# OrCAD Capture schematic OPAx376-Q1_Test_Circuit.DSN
size A; title: OPAx376-Q1 Low-Noise, Low Quiescent Current, Precision; rev: 1.4; note: Datasheet: SBOS549C EVM: N/A
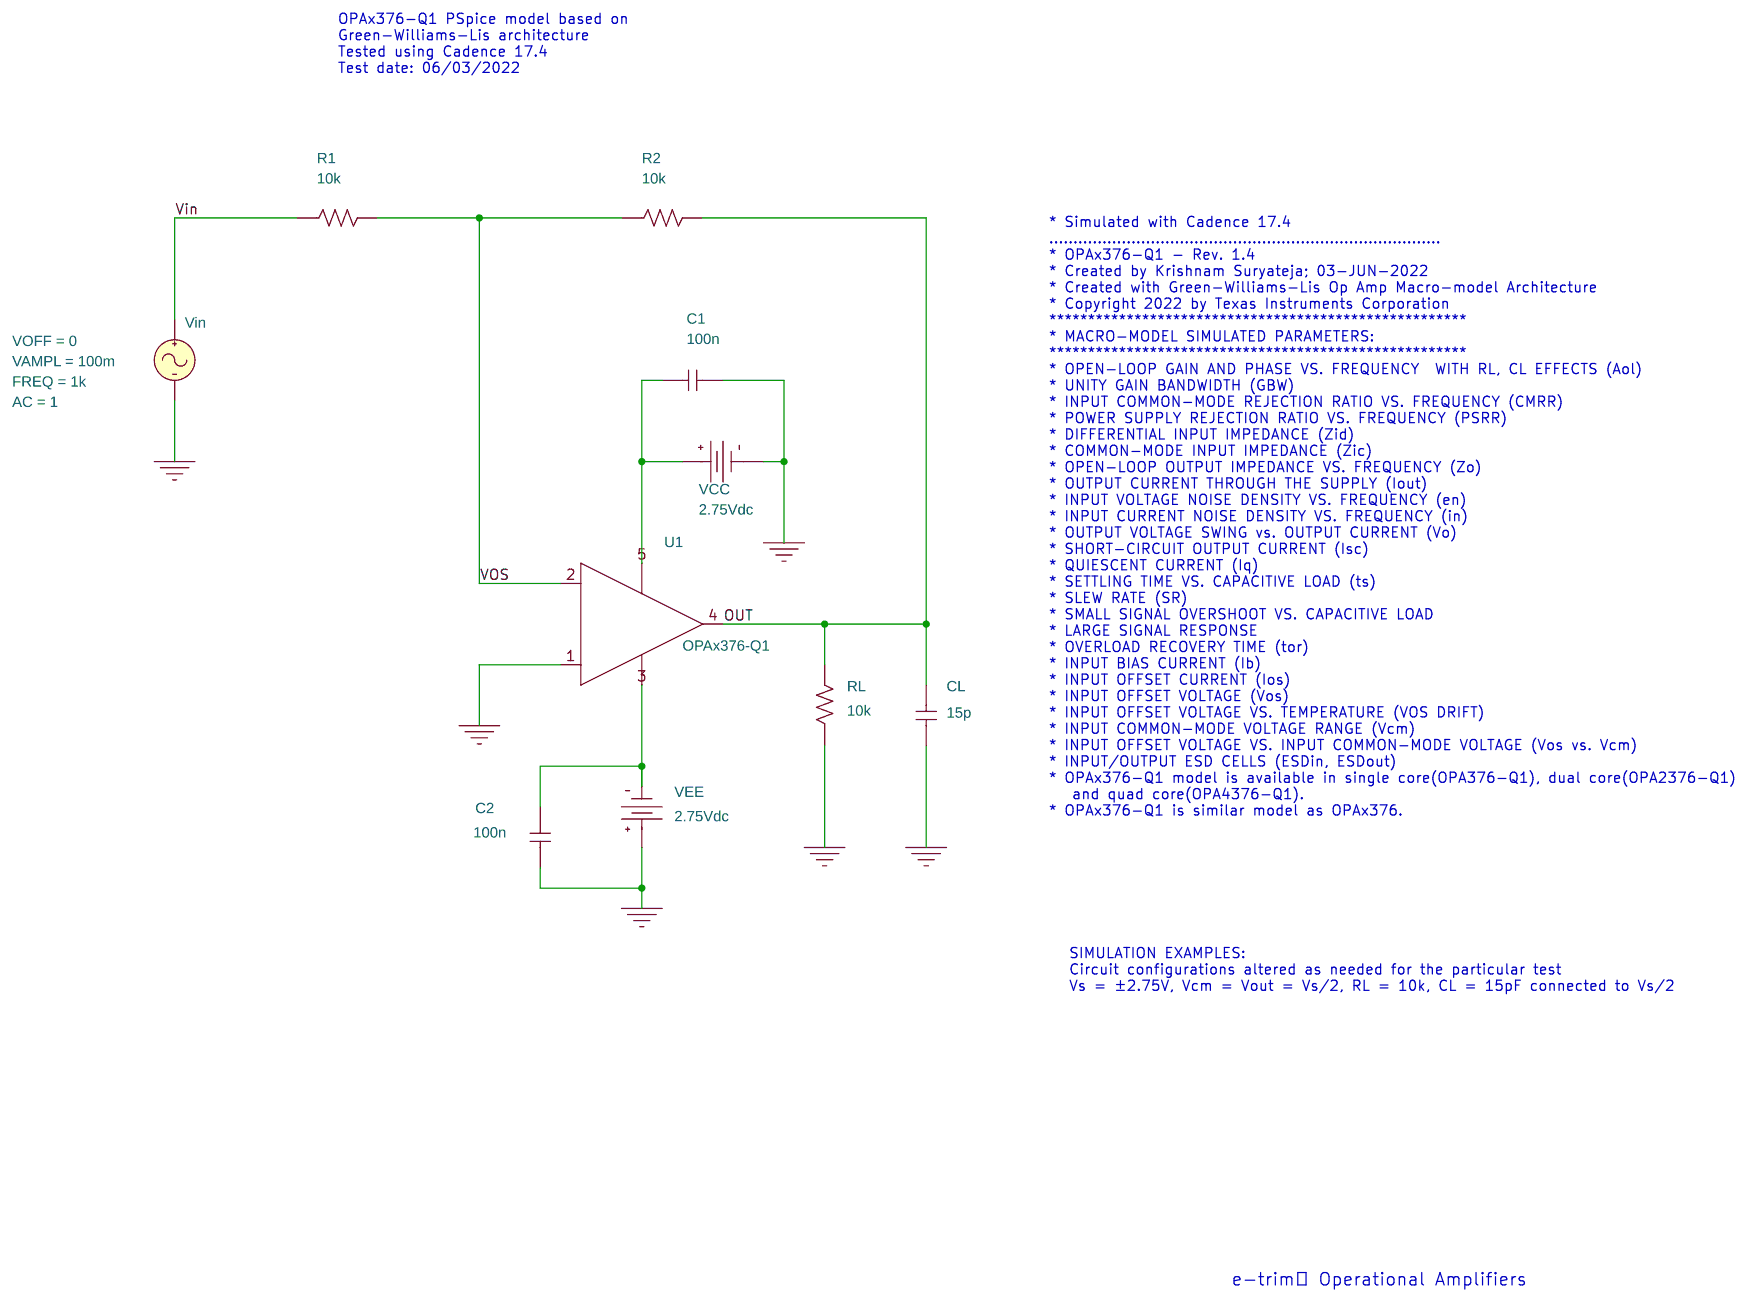
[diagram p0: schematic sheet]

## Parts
C1  100n  [cap196]
C2  100n  [cap196]
CL  15p  [cap196]
R1  10k  [AXRC05]
R2  10k  [AXRC05]
RL  10k  [AXRC05]
U1  OPAx376-Q1
VCC  VDC
VEE  VDC
Vin  VSIN

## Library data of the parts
C1 C2 CL = C
R1 R2 RL = R
U1 = OPAx376-Q1
VCC VEE = VDC: DC: 2.75Vdc
Vin = VSIN: AC: 1; FREQ: 1k; VAMPL: 100m; VOFF: 0

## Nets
Vin: R1.1 Vin.1(+)
0: C1.2 C2.1 CL.2 RL.1 U1.1(+) VCC.1(-) VEE.0(+) Vin.2(-)
OUT: CL.1 R2.2 RL.2 U1.4(OUT)
VOS: R1.2 R2.1 U1.2(-)
N27303: C1.1 U1.5(V+) VCC.0(+)
N27354: C2.2 U1.3(V-) VEE.1(-)

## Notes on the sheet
- OPAx376-Q1 PSpice model based on
  Green-Williams-Lis architecture
  Tested using Cadence 17.4
  Test date: 06/03/2022
- * Simulated with Cadence 17.4
  .................................................................................
  * OPAx376-Q1 - Rev. 1.4
  * Created by Krishnam Suryateja; 03-JUN-2022
  * Created with Green-Williams-Lis Op Amp Macro-model Architecture
  * Copyright 2022 by Texas Instruments Corporation
  ******************************************************
  * MACRO-MODEL SIMULATED PARAMETERS:
  ******************************************************
  * OPEN-LOOP GAIN AND PHASE VS. FREQUENCY  WITH RL, CL EFFECTS (Aol)
  * UNITY GAIN BANDWIDTH (GBW)
  * INPUT COMMON-MODE REJECTION RATIO VS. FREQUENCY (CMRR)
  * POWER SUPPLY REJECTION RATIO VS. FREQUENCY (PSRR)
  * DIFFERENTIAL INPUT IMPEDANCE (Zid)
  * COMMON-MODE INPUT IMPEDANCE (Zic)
  * OPEN-LOOP OUTPUT IMPEDANCE VS. FREQUENCY (Zo)
  * OUTPUT CURRENT THROUGH THE SUPPLY (Iout)
  * INPUT VOLTAGE NOISE DENSITY VS. FREQUENCY (en)
  * INPUT CURRENT NOISE DENSITY VS. FREQUENCY (in)
  * OUTPUT VOLTAGE SWING vs. OUTPUT CURRENT (Vo)
  * SHORT-CIRCUIT OUTPUT CURRENT (Isc)
  * QUIESCENT CURRENT (Iq)
  * SETTLING TIME VS. CAPACITIVE LOAD (ts)
  * SLEW RATE (SR)
  * SMALL SIGNAL OVERSHOOT VS. CAPACITIVE LOAD
  * LARGE SIGNAL RESPONSE
  * OVERLOAD RECOVERY TIME (tor)
  * INPUT BIAS CURRENT (Ib)
  * INPUT OFFSET CURRENT (Ios)
  * INPUT OFFSET VOLTAGE (Vos)
  * INPUT OFFSET VOLTAGE VS. TEMPERATURE (VOS DRIFT)
  * INPUT COMMON-MODE VOLTAGE RANGE (Vcm)
  * INPUT OFFSET VOLTAGE VS. INPUT COMMON-MODE VOLTAGE (Vos vs. Vcm)
  * INPUT/OUTPUT ESD CELLS (ESDin, ESDout)
  * OPAx376-Q1 model is available in single core(OPA376-Q1), dual core(OPA2376-Q1)
     and quad core(OPA4376-Q1).
  * OPAx376-Q1 is similar model as OPAx376.
- SIMULATION EXAMPLES:
  Circuit configurations altered as needed for the particular test
  Vs = ±2.75V, Vcm = Vout = Vs/2, RL = 10k, CL = 15pF connected to Vs/2
- e-trim™ Operational Amplifiers
